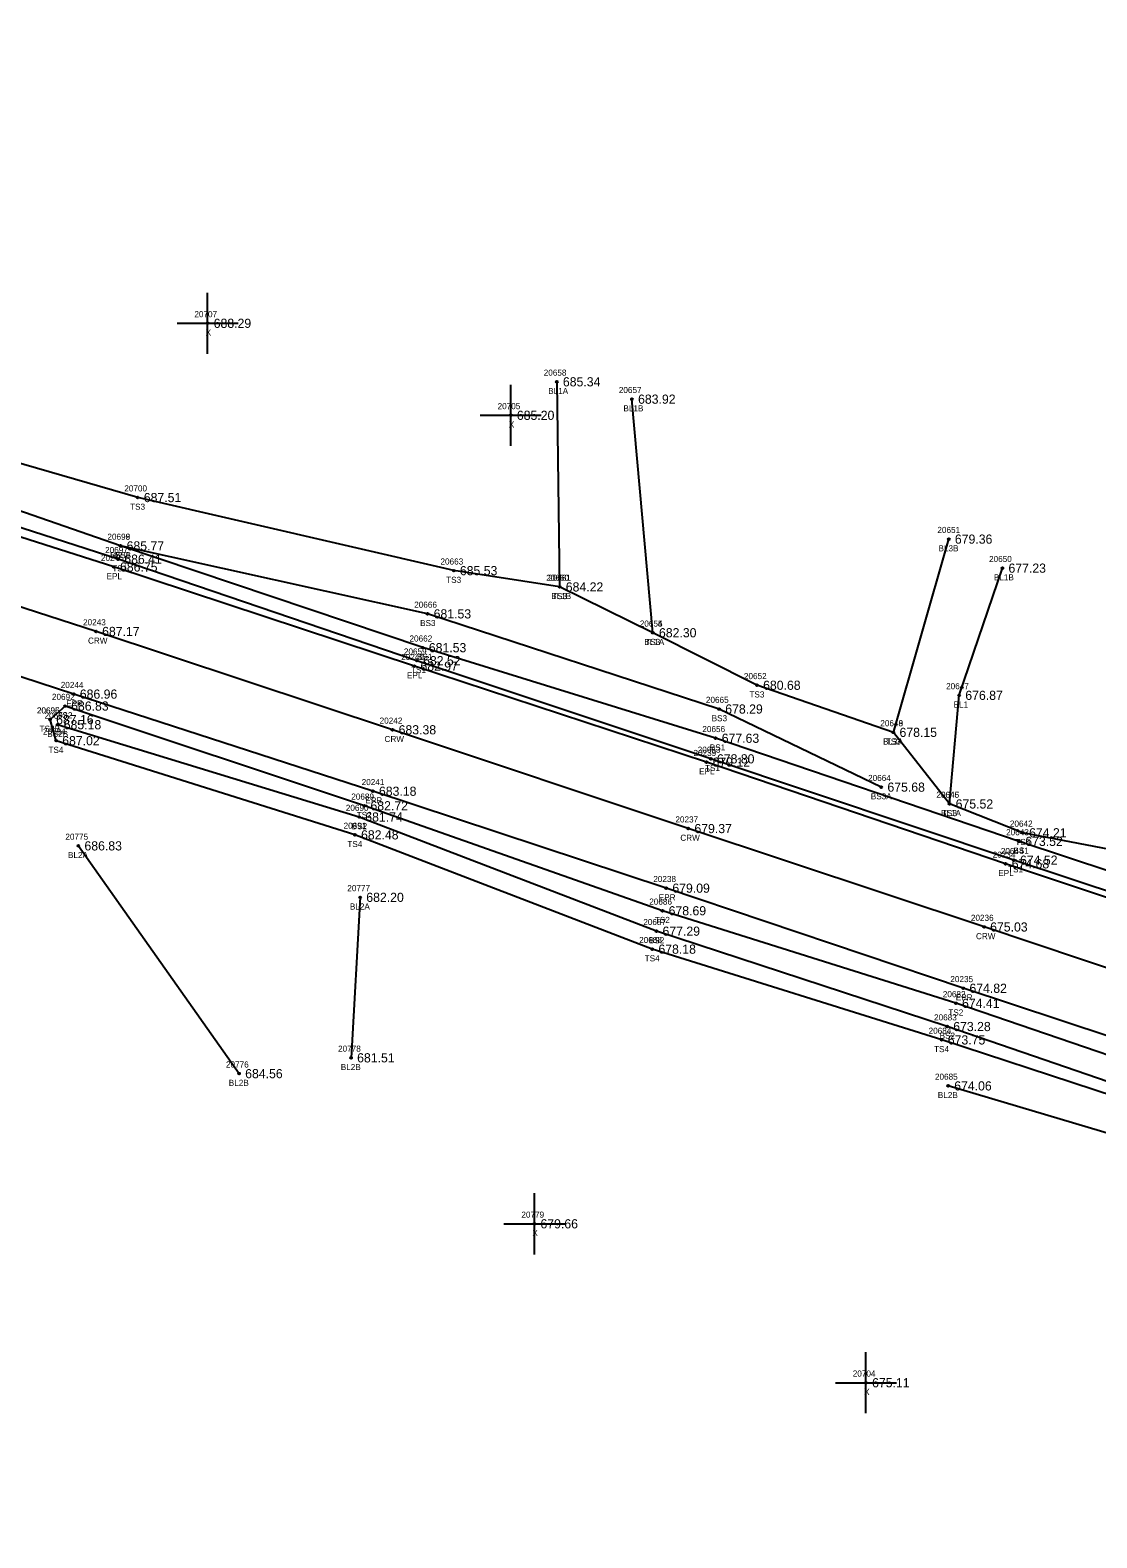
# Model space of a CAD drawing. Extents: x 1655675 to 1657082, y 1004080 to 1005193.
# Drawn here: x 1655933.5 to 1656108, y 1004619.8 to 1004866.5 of the extents above; entities that cross this region are included whole.
import ezdxf

# ---------------------------------------------------------------- set-up
doc = ezdxf.new("R2010")
doc.units = 0
for name, color, linetype in [('RD_DTM_BkLn1', 7, 'Continuous'), ('RD_DTM_BkLn2', 7, 'Continuous'), ('RD_DTM_BkLn_txCode', 7, 'Continuous'), ('RD_EX_Misc', 7, 'Continuous'), ('RD_EX_Misc_txCode', 7, 'Continuous'), ('RD_EX_Road', 7, 'Continuous'), ('RD_EX_Road_txCode', 7, 'Continuous'), ('RD_EX_TX_Misc_ELEV', 7, 'Continuous'), ('RD_EX_TX_Road_ELEV', 7, 'Continuous'), ('RD_HC_Survey_ELEV', 7, 'Continuous'), ('RD_HC_Survey_txCode', 7, 'Continuous'), ('RD_SMD_Locator', 7, 'Continuous')]:
    doc.layers.add(name, color=color, linetype=linetype)

msp = doc.modelspace()

# ---------------------------------------------------------------- linework, layer by layer
at = {"layer": 'RD_DTM_BkLn1'}
for p, q in [((1656019.67, 1004808.98), (1656020.14, 1004775.42)), ((1656035.39, 1004767.92), (1656031.97, 1004806.14)), ((1656074.75, 1004751.62), (1656083.81, 1004783.24)), ((1655941.38, 1004733.05), (1655967.68, 1004695.78)), ((1655987.5, 1004724.63), (1655986, 1004698.37))]:
    msp.add_line(p, q, dxfattribs=at)
for points in [[(1656361.94, 1004629.69), (1656332.67, 1004639.45), (1656283.94, 1004655.24), (1656235.41, 1004671.18), (1656186.64, 1004687.32), (1656138.18, 1004703.47), (1656089.58, 1004719.78), (1656041.19, 1004735.88), (1655992.79, 1004752.04), (1655944.27, 1004768.13), (1655895.76, 1004783.85), (1655847.16, 1004799.72), (1655798.63, 1004815.7), (1655750.32, 1004831.65), (1655701.73, 1004847.83)], [(1656083.94, 1004739.91), (1656085.52, 1004757.68), (1656092.58, 1004778.49)], [(1656208.24, 1004653.61), (1656178.13, 1004662.1), (1656134.11, 1004678.76), (1656083.7, 1004693.78)]]:
    msp.add_lwpolyline(points, dxfattribs=at)
at = {"layer": 'RD_DTM_BkLn2'}
for points in [[(1656169.82, 1004711.08), (1656140.99, 1004718.68), (1656095.33, 1004733.78), (1656045.66, 1004750.66), (1655997.73, 1004765.48), (1655948.28, 1004782.13), (1655899.82, 1004798.93), (1655851.52, 1004814.56), (1655803.57, 1004832.22), (1655755.82, 1004847.44), (1655708.15, 1004866.52)], [(1656170.81, 1004710.38), (1656169.05, 1004714.04), (1656155.08, 1004721.39), (1656138.53, 1004726.1), (1656123.28, 1004729.96), (1656095.95, 1004735.19), (1656083.94, 1004739.91), (1656074.75, 1004751.62), (1656052.43, 1004759.33), (1656035.39, 1004767.92), (1656020.14, 1004775.42), (1656002.81, 1004778.08), (1655951.09, 1004790.04), (1655900.95, 1004804.56), (1655853.02, 1004819.57), (1655824.47, 1004830.21), (1655817.95, 1004830.44), (1655804.69, 1004834.86), (1655792.72, 1004842.88), (1655757.63, 1004852.03), (1655728.3, 1004865.14)], [(1656170.81, 1004710.38), (1656167.78, 1004708.02), (1656140.38, 1004715.48), (1656094.47, 1004730.71), (1656044.88, 1004747.29), (1655996.79, 1004763.35), (1655947.9, 1004779.96), (1655899.03, 1004795.71), (1655850.53, 1004811.22), (1655801.91, 1004828.51), (1655755.02, 1004844.41), (1655705.18, 1004859.33)], [(1656072.77, 1004742.66), (1656046.24, 1004755.44), (1655998.52, 1004771.01), (1655948.28, 1004782.13)], [(1656222.54, 1004657.66), (1656222.26, 1004660.26), (1656181.43, 1004674.15), (1656133.46, 1004690.71), (1656084.98, 1004707.29), (1656036.97, 1004722.43), (1655988.18, 1004739.61), (1655939.2, 1004755.93), (1655936.75, 1004753.71)], [(1656222.54, 1004657.66), (1656220.66, 1004655.59), (1656178.92, 1004667.25), (1656132.32, 1004682.04), (1656132.53, 1004684.93), (1656082.65, 1004701.3), (1656035.3, 1004716.15), (1655986.64, 1004734.85), (1655937.74, 1004750.26), (1655936.75, 1004753.71)], [(1656221.55, 1004658), (1656180.42, 1004671.81), (1656132.72, 1004686.56), (1656083.54, 1004703.49), (1656035.97, 1004719.09), (1655987.33, 1004737.77), (1655937.99, 1004752.87)]]:
    msp.add_lwpolyline(points, dxfattribs=at)
at = {"layer": 'RD_EX_Misc'}
for p, q in [((1655962.53, 1004813.55), (1655962.53, 1004823.55)), ((1655957.53, 1004818.55), (1655967.53, 1004818.55)), ((1656012.14, 1004798.5), (1656012.14, 1004808.5)), ((1656007.14, 1004803.5), (1656017.14, 1004803.5)), ((1656016, 1004666.21), (1656016, 1004676.21)), ((1656011, 1004671.21), (1656021, 1004671.21)), ((1656070.26, 1004640.21), (1656070.26, 1004650.21)), ((1656065.26, 1004645.21), (1656075.26, 1004645.21))]:
    msp.add_line(p, q, dxfattribs=at)
at = {"layer": 'RD_EX_Road'}
for points in [[(1656365.12, 1004639.99), (1656336.04, 1004649.34), (1656302.55, 1004660.37), (1656279.15, 1004668.23), (1656240.07, 1004681.05), (1656188.23, 1004698.03), (1656166.72, 1004705.51), (1656141.16, 1004714.06), (1656093.11, 1004730.11), (1656044.16, 1004746.75), (1655996.36, 1004762.45), (1655947.2, 1004778.68), (1655899.09, 1004794.03), (1655850.62, 1004809.99), (1655801.91, 1004826.1), (1655753.09, 1004842.31), (1655704.25, 1004858.1)], [(1656358.5, 1004619.83), (1656328.78, 1004629.48), (1656280.77, 1004645.39), (1656247.66, 1004656.11), (1656244.5, 1004656.52), (1656222.03, 1004663.57), (1656217.65, 1004665.96), (1656183.42, 1004677.32), (1656134.59, 1004693.72), (1656086.19, 1004709.75), (1656037.58, 1004726.13), (1655989.57, 1004741.99), (1655940.62, 1004757.88), (1655892.37, 1004773.61), (1655843.48, 1004789.36), (1655805.73, 1004801.4), (1655779.22, 1004810.43), (1655768.8, 1004813.1), (1655744.59, 1004822.13), (1655698.83, 1004837.65)]]:
    msp.add_lwpolyline(points, dxfattribs=at)
at = {"layer": 'RD_SMD_Locator'}
for centre in [(1655962.53, 1004818.55), (1656019.67, 1004808.98), (1656031.97, 1004806.14), (1656012.14, 1004803.5), (1655951.09, 1004790.04), (1656083.81, 1004783.24), (1655948.28, 1004782.13), (1655948.28, 1004782.13), (1655947.2, 1004778.68), (1655947.9, 1004779.96), (1656092.58, 1004778.49), (1656002.81, 1004778.08), (1656020.14, 1004775.42), (1656020.14, 1004775.42), (1655998.52, 1004771.01), (1655944.27, 1004768.13), (1656035.39, 1004767.92), (1656035.39, 1004767.92), (1655996.79, 1004763.35), (1655997.73, 1004765.48), (1655996.36, 1004762.45), (1656052.43, 1004759.33), (1655939.2, 1004755.93), (1655940.62, 1004757.88), (1656085.52, 1004757.68), (1655936.75, 1004753.71), (1655936.75, 1004753.71), (1656046.24, 1004755.44), (1655937.99, 1004752.87), (1655992.79, 1004752.04), (1656074.75, 1004751.62), (1656074.75, 1004751.62), (1655937.74, 1004750.26), (1656045.66, 1004750.66), (1656044.16, 1004746.75), (1656044.88, 1004747.29), (1655989.57, 1004741.99), (1656072.77, 1004742.66), (1655988.18, 1004739.61), (1656083.94, 1004739.91), (1656083.94, 1004739.91), (1655987.33, 1004737.77), (1655986.64, 1004734.85), (1656041.19, 1004735.88), (1656095.33, 1004733.78), (1656095.95, 1004735.19), (1655941.38, 1004733.05), (1656093.11, 1004730.11), (1656094.47, 1004730.71), (1655987.5, 1004724.63), (1656037.58, 1004726.13), (1656036.97, 1004722.43), (1656035.97, 1004719.09), (1656089.58, 1004719.78), (1656035.3, 1004716.15), (1656086.19, 1004709.75), (1656084.98, 1004707.29), (1656083.54, 1004703.49), (1656082.65, 1004701.3), (1655986, 1004698.37), (1655967.68, 1004695.78), (1656083.7, 1004693.78), (1656016, 1004671.21), (1656070.26, 1004645.21)]:
    msp.add_circle(centre, 0.15, dxfattribs=at)

# ---------------------------------------------------------------- texts
at = {"layer": 'RD_DTM_BkLn_txCode'}
for s, p in [('20658', (1656017.53, 1004809.98)), ('BL1A', (1656018.26, 1004806.98)), ('20657', (1656029.82, 1004807.14)), ('BL1B', (1656030.57, 1004804.14)), ('20700', (1655948.9, 1004791.04)), ('TS3', (1655949.85, 1004788.04)), ('20698', (1655946.14, 1004783.13)), ('20699', (1655946.14, 1004783.13)), ('20651', (1656081.95, 1004784.24)), ('20697', (1655945.76, 1004780.96)), ('BS3B', (1655946.58, 1004780.13)), ('BS1', (1655947.34, 1004780.13)), ('BL3B', (1656082.13, 1004781.24)), ('TS1', (1655946.94, 1004777.96)), ('20663', (1656000.64, 1004779.08)), ('20650', (1656090.4, 1004779.49)), ('TS3', (1656001.57, 1004776.08)), ('20660', (1656017.94, 1004776.42)), ('20661', (1656018.26, 1004776.42)), ('BL1B', (1656091.19, 1004776.49)), ('BL1B', (1656018.75, 1004773.42)), ('TS3', (1656018.9, 1004773.42)), ('20666', (1655996.34, 1004772.01)), ('BS3', (1655997.3, 1004769.01)), ('20654', (1656033.25, 1004768.92)), ('20655', (1656033.25, 1004768.92)), ('20662', (1655995.57, 1004766.48)), ('BL1A', (1656033.98, 1004765.92)), ('TS3', (1656034.14, 1004765.92)), ('20659', (1655994.65, 1004764.35)), ('BS1', (1655996.79, 1004763.48)), ('TS1', (1655995.83, 1004761.35)), ('20652', (1656050.29, 1004760.33)), ('20647', (1656083.38, 1004758.68)), ('20692', (1655937.06, 1004756.93)), ('20665', (1656044.07, 1004756.44)), ('TS3', (1656051.19, 1004757.33)), ('BL1', (1656084.6, 1004755.68)), ('20696', (1655934.59, 1004754.71)), ('20695', (1655934.61, 1004754.71)), ('20693', (1655935.85, 1004753.87)), ('TS2', (1655937.96, 1004753.93)), ('BS3', (1656045.01, 1004753.44)), ('20648', (1656072.61, 1004752.62)), ('20649', (1656072.61, 1004752.62)), ('TS2B', (1655935.04, 1004751.71)), ('TS4B', (1655935.04, 1004751.71)), ('20694', (1655935.6, 1004751.26)), ('BS2B', (1655936.29, 1004750.87)), ('20656', (1656043.49, 1004751.66)), ('TS4', (1655936.49, 1004748.26)), ('20653', (1656042.73, 1004748.29)), ('BS1', (1656044.71, 1004748.66)), ('BL3A', (1656073.06, 1004749.62)), ('TS3', (1656073.51, 1004749.62)), ('TS1', (1656043.92, 1004745.29)), ('20664', (1656070.61, 1004743.66)), ('20689', (1655986.04, 1004740.61)), ('BS3A', (1656071.05, 1004740.66)), ('20646', (1656081.78, 1004740.91)), ('20645', (1656081.8, 1004740.91)), ('20690', (1655985.15, 1004738.77)), ('BL1A', (1656082.53, 1004737.91)), ('TS3', (1656082.7, 1004737.91)), ('20691', (1655984.78, 1004735.85)), ('BS2', (1655986.11, 1004735.77)), ('TS2', (1655986.93, 1004737.61)), ('20642', (1656093.81, 1004736.19)), ('20775', (1655939.26, 1004734.05)), ('TS4', (1655985.4, 1004732.85)), ('20643', (1656093.19, 1004734.78)), ('TS3', (1656094.71, 1004733.19)), ('BL2A', (1655939.68, 1004731.05)), ('20644', (1656092.33, 1004731.71)), ('BS1', (1656094.39, 1004731.78)), ('TS1', (1656093.51, 1004728.71)), ('20777', (1655985.39, 1004725.63)), ('20686', (1656034.8, 1004723.43)), ('BL2A', (1655985.81, 1004722.63)), ('20687', (1656033.82, 1004720.09)), ('TS2', (1656035.72, 1004720.43)), ('20688', (1656033.15, 1004717.15)), ('BS2', (1656034.74, 1004717.09)), ('TS4', (1656034.05, 1004714.15)), ('20682', (1656082.84, 1004708.29)), ('20683', (1656081.4, 1004704.49)), ('TS2', (1656083.74, 1004705.29)), ('20684', (1656080.51, 1004702.3)), ('BS2', (1656082.31, 1004701.49)), ('20778', (1655983.88, 1004699.37)), ('TS4', (1656081.4, 1004699.3)), ('20776', (1655965.54, 1004696.78)), ('BL2B', (1655984.32, 1004696.37)), ('BL2B', (1655966, 1004693.78)), ('20685', (1656081.55, 1004694.78)), ('BL2B', (1656082.02, 1004691.78))]:
    msp.add_text(s, height=1, dxfattribs=at).set_placement(p)
at = {"layer": 'RD_EX_Misc_txCode'}
for s, p in [('20707', (1655960.37, 1004819.55)), ('X', (1655962.21, 1004816.55)), ('20705', (1656009.98, 1004804.5)), ('X', (1656011.82, 1004801.5)), ('20779', (1656013.88, 1004672.21)), ('X', (1656015.68, 1004669.21)), ('20704', (1656068.1, 1004646.21)), ('X', (1656069.95, 1004643.21))]:
    msp.add_text(s, height=1, dxfattribs=at).set_placement(p)
at = {"layer": 'RD_EX_Road_txCode'}
for s, p in [('20245', (1655945.08, 1004779.68)), ('EPL', (1655945.99, 1004776.68)), ('20240', (1655994.2, 1004763.45)), ('EPL', (1655995.15, 1004760.45)), ('20244', (1655938.5, 1004758.88)), ('EPR', (1655939.39, 1004755.88)), ('20239', (1656042.04, 1004747.75)), ('20241', (1655987.74, 1004742.99)), ('EPL', (1656042.96, 1004744.75)), ('EPR', (1655988.35, 1004739.99)), ('20234', (1656091, 1004731.11)), ('EPL', (1656091.91, 1004728.11)), ('20238', (1656035.46, 1004727.13)), ('EPR', (1656036.35, 1004724.13)), ('20235', (1656084.07, 1004710.75)), ('EPR', (1656084.96, 1004707.75))]:
    msp.add_text(s, height=1, dxfattribs=at).set_placement(p)
at = {"layer": 'RD_EX_TX_Misc_ELEV'}
for s, p in [('688.29', (1655963.53, 1004817.8)), ('685.34', (1656020.67, 1004808.23)), ('683.92', (1656032.97, 1004805.39)), ('685.20', (1656013.14, 1004802.75)), ('687.51', (1655952.09, 1004789.29)), ('679.36', (1656084.81, 1004782.49)), ('686.41', (1655948.9, 1004779.21)), ('685.77', (1655949.28, 1004781.38)), ('685.77', (1655949.28, 1004781.38)), ('685.53', (1656003.81, 1004777.33)), ('677.23', (1656093.58, 1004777.74)), ('684.22', (1656021.14, 1004774.67)), ('684.22', (1656021.14, 1004774.67)), ('681.53', (1655999.52, 1004770.26)), ('682.30', (1656036.39, 1004767.17)), ('682.30', (1656036.39, 1004767.17)), ('681.53', (1655998.73, 1004764.73)), ('682.52', (1655997.79, 1004762.6)), ('680.68', (1656053.43, 1004758.58)), ('686.83', (1655940.2, 1004755.18)), ('678.29', (1656047.24, 1004754.69)), ('676.87', (1656086.52, 1004756.93)), ('687.16', (1655937.75, 1004752.96)), ('687.16', (1655937.75, 1004752.96)), ('685.18', (1655938.99, 1004752.12)), ('677.63', (1656046.66, 1004749.91)), ('678.15', (1656075.75, 1004750.87)), ('678.15', (1656075.75, 1004750.87)), ('687.02', (1655938.74, 1004749.51)), ('678.80', (1656045.88, 1004746.54)), ('675.68', (1656073.77, 1004741.91)), ('682.72', (1655989.18, 1004738.86)), ('675.52', (1656084.94, 1004739.16)), ('675.52', (1656084.94, 1004739.16)), ('681.74', (1655988.33, 1004737.02)), ('682.48', (1655987.64, 1004734.1)), ('673.52', (1656096.33, 1004733.03)), ('674.21', (1656096.95, 1004734.44)), ('686.83', (1655942.38, 1004732.3)), ('674.52', (1656095.47, 1004729.96)), ('682.20', (1655988.5, 1004723.88)), ('678.69', (1656037.97, 1004721.68)), ('677.29', (1656036.97, 1004718.34)), ('678.18', (1656036.3, 1004715.4)), ('674.41', (1656085.98, 1004706.54)), ('673.28', (1656084.54, 1004702.74)), ('673.75', (1656083.65, 1004700.55)), ('681.51', (1655987, 1004697.62)), ('684.56', (1655968.68, 1004695.03)), ('674.06', (1656084.7, 1004693.03)), ('679.66', (1656017, 1004670.46)), ('675.11', (1656071.26, 1004644.46))]:
    msp.add_text(s, height=1.5, dxfattribs=at).set_placement(p)
at = {"layer": 'RD_EX_TX_Road_ELEV'}
for s, p in [('686.75', (1655948.2, 1004777.93)), ('682.97', (1655997.36, 1004761.7)), ('686.96', (1655941.62, 1004757.13)), ('679.12', (1656045.16, 1004746)), ('683.18', (1655990.57, 1004741.24)), ('674.68', (1656094.11, 1004729.36)), ('679.09', (1656038.58, 1004725.38)), ('674.82', (1656087.19, 1004709))]:
    msp.add_text(s, height=1.5, dxfattribs=at).set_placement(p)
at = {"layer": 'RD_HC_Survey_ELEV'}
for s, p in [('687.17', (1655945.27, 1004767.38)), ('683.38', (1655993.79, 1004751.29)), ('679.37', (1656042.19, 1004735.13)), ('675.03', (1656090.58, 1004719.03))]:
    msp.add_text(s, height=1.5, dxfattribs=at).set_placement(p)
at = {"layer": 'RD_HC_Survey_txCode'}
for s, p in [('20243', (1655942.15, 1004769.13)), ('CRW', (1655942.96, 1004766.13)), ('20242', (1655990.68, 1004753.04)), ('CRW', (1655991.48, 1004750.04)), ('20237', (1656039.08, 1004736.88)), ('CRW', (1656039.88, 1004733.88)), ('20236', (1656087.43, 1004720.78)), ('CRW', (1656088.26, 1004717.78))]:
    msp.add_text(s, height=1, dxfattribs=at).set_placement(p)

doc.saveas('drawing.dxf')
